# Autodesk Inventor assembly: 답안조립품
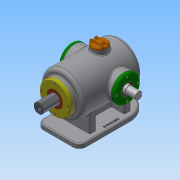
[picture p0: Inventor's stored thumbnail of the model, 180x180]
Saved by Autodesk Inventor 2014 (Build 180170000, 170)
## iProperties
Created: 2018-04
Part Number: 답안조립품
Document SubType Name: Assembly
Designer: net
Mass: 5764.01 g
Surface Area: 4274.04 cm^2
Volume: 2081.36 cm^3
Density: 2.76935 g/cm^3
Author: net
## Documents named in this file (17)
- C:\Users\net\Desktop\380407V1007\답안조립품.iam
- C:\Users\net\Desktop\380407V1007\플레이트.ipt
- C:\Users\net\Desktop\380407V1007\본체.ipt
- C:\Users\net\Desktop\380407V1007\베어링 6205.ipt
- 베어링 6205.ipt
- C:\Users\net\Desktop\380407V1007\축 커버-1.ipt
- C:\Users\net\Desktop\380407V1007\축 커버-2.ipt
- C:\Users\net\Desktop\380407V1007\오일실.ipt
- 오일실.ipt
- C:\Users\net\Desktop\380407V1007\슬라이드 커버.ipt
- C:\Users\net\Desktop\380407V1007\부시.ipt
- C:\Users\net\Desktop\380407V1007\편심축.ipt
- C:\Users\net\Desktop\380407V1007\슬라이드.ipt
- C:\Users\net\Desktop\380407V1007\볼트 M4.ipt
- 볼트 M4.ipt
- C:\Users\net\Desktop\380407V1007\상부 캡.ipt
- C:\Users\net\Desktop\380407V1007\가변스프링.ipt
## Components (2 placed, 2 different names)
1. 플레이트:1
2. 가변스프링:1
